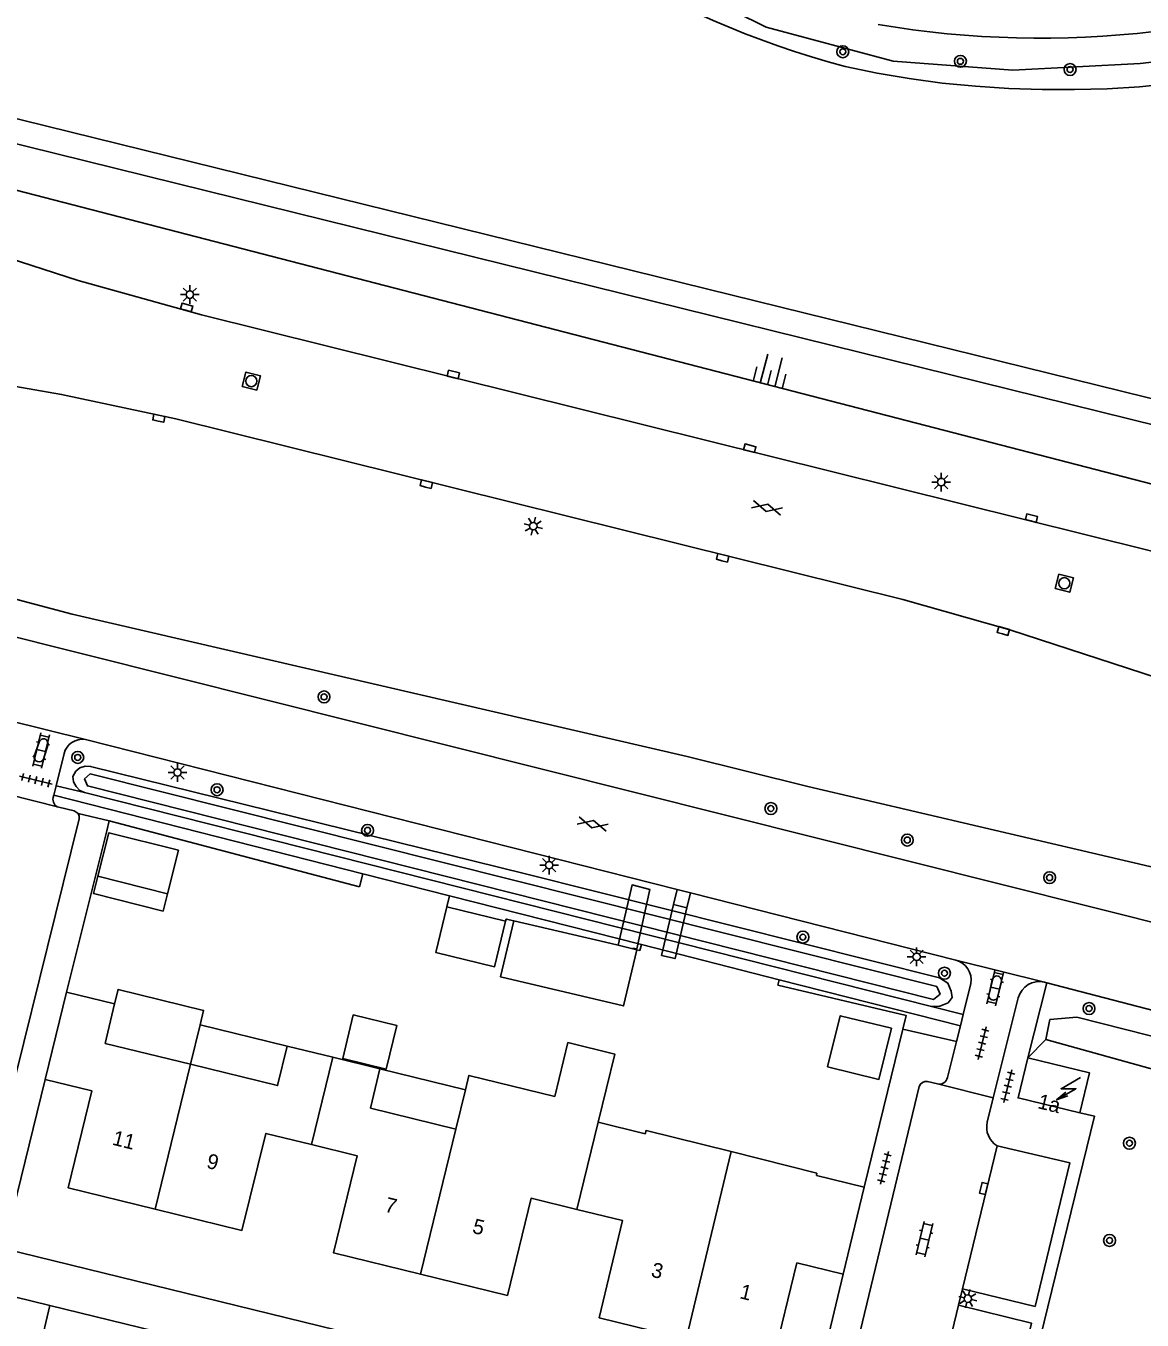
# Model space of a CAD drawing. Extents: x 128000 to 131008, y 398996 to 402500.
# Drawn here: x 128513.5 to 128588.3, y 399557.4 to 399644.1 of the extents above; entities that cross this region are included whole.
import ezdxf

# ---------------------------------------------------------------- set-up
doc = ezdxf.new("R2010")
doc.units = 0
for name, color, linetype in [('gg-afsc-erfafscheiding', 7, 'Continuous'), ('gg-afsc-muur', 7, 'Continuous'), ('gg-anno-huisnummerreeks BGT', 7, 'Continuous'), ('gg-bbg-gedigitaliseerde bebouwing', 7, 'Continuous'), ('gg-bbg-gedigitaliseerde bijgebouw', 7, 'Continuous'), ('gg-bbg-hoofdgebouw', 7, 'Continuous'), ('gg-bbg-luifel en loopbrug', 7, 'Continuous'), ('gg-bbg-tussenscheiding', 7, 'Continuous'), ('gg-knt-BGT kruinlijn', 7, 'Continuous'), ('gg-knt-onverhard', 7, 'Continuous'), ('gg-knt-verharding', 7, 'Continuous'), ('gg-knt-verharding nz', 7, 'Continuous'), ('gg-kntw-beschoeiing', 7, 'Continuous'), ('gg-kntw-bovenkant insteek waterloop', 7, 'Continuous'), ('gg-kntw-greppel-droge sloot', 7, 'Continuous'), ('gg-kntw-midden sloot', 7, 'Continuous'), ('gg-kntw-waterlijn', 7, 'Continuous'), ('gg-kwrk-kunstwerk niveau 01', 7, 'Continuous'), ('gt-grn-groengrens', 7, 'Continuous'), ('gt-grn-groengrens NZ', 7, 'Continuous'), ('gt-symb-boom', 7, 'Continuous'), ('gt-symb-gesloten verharding', 7, 'Continuous'), ('gt-symb-klinker verharding', 7, 'Continuous'), ('gt-symb-kolk', 7, 'Continuous'), ('gt-symb-lichtmast', 7, 'Continuous'), ('gt-symb-rioolschacht', 7, 'Continuous'), ('gt-symb-talud symbool', 7, 'Continuous'), ('gt-symb-tegel verharding', 7, 'Continuous'), ('gt-symb-trafo symbool', 7, 'Continuous')]:
    doc.layers.add(name, color=color, linetype=linetype)

# ---------------------------------------------------------------- blocks, each defined once
blk = doc.blocks.new('gt0-BOOM')
at = {"layer": 'gt-symb-boom'}
for radius in [0.4, 0.2]:
    blk.add_circle((0, 0), radius, dxfattribs=at)
blk = doc.blocks.new('gt0-KL1')
at = {"layer": 'gt-symb-klinker verharding'}
for p, q in [((-1.15, 0.3), (1.15, 0.3)), ((-1, -0.3), (-1, 0.3)), ((-0.5, 0.3), (-0.5, 0.45)), ((0, -0.3), (0, 0.3)), ((0.5, 0.3), (0.5, 0.45)), ((1, -0.3), (1, 0.3)), ((-1.15, -0.3), (1.15, -0.3)), ((-0.5, -0.45), (-0.5, -0.3)), ((0.5, -0.45), (0.5, -0.3))]:
    blk.add_line(p, q, dxfattribs=at)
blk = doc.blocks.new('gt0-TEG1')
at = {"layer": 'gt-symb-tegel verharding'}
for p, q in [((-1.125, 0), (1.125, 0)), ((-0.9, -0.25), (-0.9, 0.25)), ((-0.45, -0.25), (-0.45, 0.25)), ((0, -0.25), (0, 0.25)), ((0.45, -0.25), (0.45, 0.25)), ((0.9, -0.25), (0.9, 0.25))]:
    blk.add_line(p, q, dxfattribs=at)
blk = doc.blocks.new('gt0-LMAST')
at = {"layer": 'gt-symb-lichtmast'}
for p, q in [((-0.182, 0.173), (-0.447, 0.438)), ((-0.005, 0.246), (-0.005, 0.621)), ((0.172, 0.173), (0.437, 0.438)), ((-0.255, -0.004), (-0.63, -0.004)), ((-0.182, -0.181), (-0.447, -0.446)), ((-0.005, -0.254), (-0.005, -0.629)), ((0.437, -0.446), (0.172, -0.181)), ((0.245, -0.004), (0.62, -0.004))]:
    blk.add_line(p, q, dxfattribs=at)
blk.add_circle((-0.005, -0.004), 0.25, dxfattribs=at)
blk = doc.blocks.new('gt0-KOLK')
at = {"layer": 'gt-symb-kolk'}
blk.add_lwpolyline([(0, 0), (0.375, 0), (0.375, 0.4), (-0.375, 0.4), (-0.375, 0), (0, 0)], dxfattribs=at)
blk = doc.blocks.new('gt0-TALUD_1')
at = {"layer": 'gt-symb-talud symbool'}
for p, q in [((-1, -1), (-1, 0)), ((-0.5, -2), (-0.5, 0)), ((0.5, -2), (0.5, 0)), ((1, -1), (1, 0)), ((0, -1), (0, 0))]:
    blk.add_line(p, q, dxfattribs=at)
blk = doc.blocks.new('gt0-RS')
at = {"layer": 'gt-symb-rioolschacht'}
blk.add_lwpolyline([(-0.5, -0.5), (0.5, -0.5), (0.5, 0.5), (-0.5, 0.5)], close=True, dxfattribs=at)
blk.add_circle((0, 0), 0.375, dxfattribs=at)
blk = doc.blocks.new('gt0-GESVH1')
at = {"layer": 'gt-symb-gesloten verharding'}
for p, q in [((-0.992, -0.261), (0.008, 0.239)), ((0.008, -0.261), (-0.992, 0.239)), ((0.008, 0.239), (1.008, -0.261)), ((1.008, 0.239), (0.008, -0.261))]:
    blk.add_line(p, q, dxfattribs=at)
blk = doc.blocks.new('gt0-HSP')
at = {"layer": 'gt-symb-trafo symbool'}
for points in [[(0.771, 0.746), (-0.529, -0.004), (0.471, -0.004), (-0.829, -0.754)], [(-0.217, -0.24), (-0.829, -0.754), (-0.077, -0.48)]]:
    blk.add_lwpolyline(points, dxfattribs=at)

msp = doc.modelspace()

# ---------------------------------------------------------------- linework, layer by layer
at = {"layer": 'gg-afsc-erfafscheiding'}
for p, q in [((128519.13, 399590.87), (128535.897, 399586.464)), ((128518.964, 399590.205), (128516.27, 399579.4))]:
    msp.add_line(p, q, dxfattribs=at)
msp.add_lwpolyline([(128572.28, 399576.92), (128572.504, 399577.833), (128563.909, 399579.863)], dxfattribs=at)
at = {"layer": 'gg-afsc-muur'}
for p, q in [((128554.668, 399582.188), (128554.465, 399582.237)), ((128569.69, 399566.34), (128572.28, 399576.92))]:
    msp.add_line(p, q, dxfattribs=at)
msp.add_lwpolyline([(128546.226, 399584.179), (128545.717, 399584.298), (128545.673, 399584.166)], dxfattribs=at)
at = {"layer": 'gg-bbg-gedigitaliseerde bebouwing'}
for p, q in [((128524.568, 399574.573), (128518.85, 399575.97)), ((128534.107, 399575.04), (128531.051, 399575.786)), ((128537.26, 399574.27), (128534.107, 399575.04)), ((128536.62, 399571.63), (128537.26, 399574.27)), ((128542.986, 399572.868), (128542.339, 399570.228)), ((128536.62, 399571.63), (128542.339, 399570.228)), ((128551.868, 399570.693), (128555.03, 399569.92)), ((128566.527, 399567.265), (128560.782, 399568.731))]:
    msp.add_line(p, q, dxfattribs=at)
for points in [[(128524.568, 399574.573), (128530.404, 399573.144), (128531.051, 399575.786)], [(128551.868, 399570.693), (128552.987, 399575.255), (128549.849, 399576.025), (128548.964, 399572.413), (128543.22, 399573.822), (128542.986, 399572.868)], [(128560.782, 399568.731), (128555.081, 399570.129), (128555.03, 399569.92)]]:
    msp.add_lwpolyline(points, dxfattribs=at)
at = {"layer": 'gg-bbg-gedigitaliseerde bijgebouw'}
msp.add_line((128523.029, 399585.993), (128518.374, 399587.166), dxfattribs=at)
msp.add_lwpolyline([(128523.029, 399585.993), (128523.761, 399588.903), (128519.107, 399590.075), (128518.374, 399587.166)], dxfattribs=at)
at = {"layer": 'gg-bbg-hoofdgebouw'}
for p, q in [((128516.27, 399579.4), (128514.84, 399573.56)), ((128519.49, 399578.61), (128516.27, 399579.4)), ((128518.85, 399575.97), (128519.49, 399578.61)), ((128566.49, 399567.12), (128566.527, 399567.265)), ((128569.69, 399566.34), (128566.49, 399567.12)), ((128568.29, 399560.5), (128569.69, 399566.34))]:
    msp.add_line(p, q, dxfattribs=at)
for points in [[(128580.64, 399575.001), (128580, 399572.32), (128584.13, 399571.32)], [(128584.13, 399571.32), (128584.77, 399574), (128580.64, 399575.001)], [(128514.84, 399573.56), (128517.97, 399572.79), (128516.38, 399566.3), (128522.203, 399564.869)], [(128522.203, 399564.869), (128528.02, 399563.44), (128529.62, 399569.94), (128532.674, 399569.19)], [(128532.674, 399569.19), (128535.73, 399568.44), (128534.14, 399561.94), (128539.968, 399560.516)], [(128539.968, 399560.516), (128545.8, 399559.09), (128547.38, 399565.59), (128550.44, 399564.846)], [(128550.44, 399564.846), (128553.51, 399564.1), (128551.93, 399557.59), (128557.768, 399556.164)], [(128557.768, 399556.164), (128563.6, 399554.74), (128565.18, 399561.26), (128568.29, 399560.5)]]:
    msp.add_lwpolyline(points, dxfattribs=at)
at = {"layer": 'gg-bbg-luifel en loopbrug'}
for p, q in [((128541.738, 399585.109), (128545.673, 399584.166)), ((128550.817, 399583.102), (128546.226, 399584.179)), ((128551.993, 399582.837), (128550.817, 399583.102)), ((128553.221, 399582.539), (128551.993, 399582.837)), ((128554.195, 399582.303), (128553.221, 399582.539)), ((128554.465, 399582.237), (128554.195, 399582.303)), ((128525.212, 399577.211), (128524.568, 399574.573)), ((128525.212, 399577.211), (128531.051, 399575.786)), ((128537.26, 399574.27), (128542.986, 399572.868))]:
    msp.add_line(p, q, dxfattribs=at)
for points in [[(128518.374, 399587.166), (128518.081, 399586.002), (128522.736, 399584.83), (128523.029, 399585.993)], [(128545.673, 399584.166), (128544.94, 399581.104), (128541.005, 399582.047), (128541.738, 399585.109)], [(128546.226, 399584.179), (128545.34, 399580.418), (128553.578, 399578.476), (128554.465, 399582.237)], [(128519.49, 399578.61), (128519.728, 399579.581), (128525.449, 399578.181), (128525.212, 399577.211)], [(128535.47, 399577.871), (128538.387, 399577.168), (128537.684, 399574.252), (128534.767, 399574.955), (128535.47, 399577.871)], [(128567.242, 399574.39), (128570.671, 399573.551), (128571.51, 399576.979), (128568.081, 399577.819), (128567.242, 399574.39)]]:
    msp.add_lwpolyline(points, dxfattribs=at)
at = {"layer": 'gg-bbg-tussenscheiding'}
for p, q in [((128532.674, 399569.19), (128534.107, 399575.04)), ((128522.203, 399564.869), (128524.568, 399574.573)), ((128550.44, 399564.846), (128551.868, 399570.693)), ((128539.968, 399560.516), (128542.339, 399570.228)), ((128557.768, 399556.164), (128560.782, 399568.731))]:
    msp.add_line(p, q, dxfattribs=at)
at = {"layer": 'gg-knt-BGT kruinlijn'}
msp.add_line((128502.498, 399635.812), (128623.42, 399604.526), dxfattribs=at)
at = {"layer": 'gg-knt-onverhard'}
msp.add_arc((128581.493, 399708.045), 64.741, 260.34403, 293.17735, dxfattribs=at)
at = {"layer": 'gg-knt-verharding'}
for p, q in [((128512.32, 399597.621), (128517.537, 399596.321)), ((128514.438, 399596.141), (128514.1, 399595.22)), ((128514.738, 399595.011), (128515.03, 399596.02)), ((128557.167, 399586.28), (128517.537, 399596.321)), ((128516.109, 399595.381), (128515.577, 399593.233)), ((128515.577, 399593.233), (128515.42, 399592.601)), ((128515.751, 399591.786), (128512.322, 399592.66)), ((128515.42, 399592.601), (128515.38, 399592.44)), ((128517.04, 399591.361), (128519.13, 399590.87)), ((128519.13, 399590.87), (128518.964, 399590.205)), ((128556.91, 399585.263), (128557.167, 399586.28)), ((128558.066, 399586.052), (128557.167, 399586.28)), ((128558.066, 399586.052), (128557.813, 399585.052)), ((128575.83, 399581.551), (128558.066, 399586.052)), ((128575.83, 399581.551), (128581.769, 399580.078)), ((128578.269, 399580.231), (128578.05, 399579.26)), ((128576.321, 399577.904), (128576.84, 399579.99)), ((128578.64, 399579.101), (128578.879, 399580.081)), ((128581.93, 399580.03), (128580.64, 399575.001)), ((128581.93, 399580.03), (128581.769, 399580.078)), ((128578.336, 399572.314), (128580.01, 399579.02)), ((128576.133, 399577.147), (128576.321, 399577.904)), ((128572.28, 399576.92), (128575.87, 399576.09)), ((128575.87, 399576.09), (128576.133, 399577.147)), ((128575.87, 399576.09), (128575.26, 399573.68)), ((128514.84, 399573.56), (128512.692, 399564.8)), ((128573.94, 399573.41), (128574.6, 399573.25)), ((128574.6, 399573.25), (128578.336, 399572.314)), ((128568.1, 399551.17), (128573.38, 399573.081)), ((128578.336, 399572.314), (128577.93, 399570.69)), ((128565.53, 399549.13), (128568.29, 399560.5)), ((128509.44, 399559.817), (128515.154, 399558.42)), ((128576.009, 399558.428), (128576.277, 399559.533)), ((128515.154, 399558.42), (128514.012, 399553.54)), ((128515.154, 399558.42), (128564.831, 399546.272))]:
    msp.add_line(p, q, dxfattribs=at)
for points in [[(128492.703, 399634.461), (128499.462, 399632.565), (128506.196, 399630.581), (128517.05, 399627.08), (128525.32, 399624.77), (128614.18, 399602.67), (128618.463, 399601.732), (128622.829, 399600.968)], [(128621.03, 399590.124), (128579.44, 399603.67), (128572.28, 399605.7), (128523.59, 399617.81), (128515.94, 399619.44), (128501.631, 399621.928), (128497.943, 399622.631)], [(128615.399, 399576.485), (128615.66, 399577.39), (128480.487, 399611.313)], [(128517.04, 399591.361), (128517.113, 399591.188), (128517.11, 399591.001), (128510.73, 399565.281)], [(128517.04, 399591.361), (128516.78, 399591.54), (128515.751, 399591.786)], [(128581.93, 399580.03), (128614.01, 399571.67), (128614.22, 399572.399)], [(128580.17, 399550.92), (128585.11, 399571.1), (128584.13, 399571.32)], [(128578.593, 399569.113), (128583.47, 399567.964), (128581.132, 399558.353), (128576.277, 399559.533)], [(128512.692, 399564.8), (128512.06, 399562.22), (128565.53, 399549.13)], [(128574.86, 399553.679), (128579.725, 399552.487), (128580.89, 399557.235), (128576.009, 399558.428)]]:
    msp.add_lwpolyline(points, dxfattribs=at)
for centre, radius, start, end in [((128514.731, 399596.063), 0.303, 351.73795, 165.15868), ((128517.32, 399595.096), 1.244, 79.97078, 166.74011), ((128514.435, 399595.164), 0.339, 170.43309, 333.29075), ((128515.903, 399592.304), 0.54, 165.47107, 253.65953), ((128575.472, 399580.212), 1.386, 350.76647, 75.04097), ((128578.577, 399580.169), 0.314, 343.80237, 168.56758), ((128581.438, 399578.636), 1.479, 77.08195, 164.97002), ((128578.344, 399579.175), 0.306, 163.8584, 345.97676), ((128573.85, 399572.922), 0.496, 79.5634, 161.30507), ((128574.723, 399573.783), 0.547, 257.06343, 349.10627), ((128579.34, 399570.355), 1.449, 166.62051, 238.98506)]:
    msp.add_arc(centre, radius, start, end, dxfattribs=at)
at = {"layer": 'gg-knt-verharding nz'}
for p, q in [((128576.277, 399559.533), (128578.593, 399569.113)), ((128574.86, 399553.679), (128576.009, 399558.428))]:
    msp.add_line(p, q, dxfattribs=at)
at = {"layer": 'gg-kntw-beschoeiing'}
msp.add_line((128502.74, 399640.42), (128622.506, 399610.89), dxfattribs=at)
for points in [[(128607.536, 399644.895), (128605.5, 399644.006), (128603.423, 399643.22), (128601.309, 399642.538), (128597.001, 399641.408), (128594.78, 399640.947), (128592.544, 399640.566), (128590.296, 399640.264), (128588.13, 399640.053), (128585.957, 399639.923), (128583.781, 399639.867), (128581.604, 399639.874), (128579.371, 399639.946), (128577.14, 399640.081), (128574.915, 399640.293), (128572.701, 399640.596)], [(128572.701, 399640.596), (128570.556, 399640.971), (128568.423, 399641.42)]]:
    msp.add_lwpolyline(points, dxfattribs=at)
msp.add_arc((128583.808, 399699.986), 60.553, 185.69458, 255.28175, dxfattribs=at)
at = {"layer": 'gg-kntw-bovenkant insteek waterloop'}
msp.add_line((128517.485, 399592.784), (128574.196, 399578.433), dxfattribs=at)
msp.add_lwpolyline([(128574.196, 399578.433), (128574.761, 399578.463), (128575.311, 399578.686), (128575.578, 399579.043), (128575.519, 399579.474), (128575.296, 399580.009), (128574.731, 399580.366), (128547.012, 399587.316), (128517.883, 399594.524), (128517.51, 399594.549), (128517.162, 399594.424), (128516.889, 399594.201), (128516.691, 399593.853), (128516.74, 399593.48), (128516.914, 399593.181), (128517.162, 399592.908), (128517.485, 399592.784)], dxfattribs=at)
at = {"layer": 'gg-kntw-greppel-droge sloot'}
for points in [[(128583.934, 399577.729), (128582.124, 399577.558), (128581.854, 399576.218)], [(128635.847, 399563.256), (128636.073, 399564.317), (128614.401, 399569.99), (128583.934, 399577.729)], [(128581.854, 399576.218), (128613.011, 399567.574), (128614.344, 399568.095), (128635.847, 399563.256)]]:
    msp.add_lwpolyline(points, dxfattribs=at)
at = {"layer": 'gg-kntw-midden sloot'}
msp.add_lwpolyline([(128499.736, 399609.202), (128516.644, 399604.724), (128557.833, 399595.187), (128565.918, 399593.182), (128588.829, 399587.823), (128601.71, 399584.632), (128619.44, 399580.541)], dxfattribs=at)
at = {"layer": 'gg-kntw-waterlijn'}
msp.add_lwpolyline([(128517.852, 399594.035), (128574.545, 399579.785), (128574.775, 399579.272), (128574.339, 399578.9), (128517.664, 399593.219), (128517.475, 399593.7), (128517.852, 399594.035)], dxfattribs=at)
at = {"layer": 'gg-kwrk-kunstwerk niveau 01'}
msp.add_line((128557.813, 399585.052), (128556.91, 399585.263), dxfattribs=at)
for points in [[(128553.221, 399582.539), (128554.144, 399586.584), (128555.325, 399586.288), (128554.455, 399582.293), (128554.202, 399582.339), (128554.195, 399582.303)], [(128557.813, 399585.052), (128557.023, 399581.653), (128556.12, 399581.864), (128556.91, 399585.263)]]:
    msp.add_lwpolyline(points, dxfattribs=at)
at = {"layer": 'gt-grn-groengrens'}
for p, q in [((128515.577, 399593.233), (128517.485, 399592.784)), ((128536.118, 399587.333), (128515.42, 399592.601)), ((128535.897, 399586.464), (128536.118, 399587.333)), ((128541.928, 399585.854), (128536.118, 399587.333)), ((128541.738, 399585.109), (128541.928, 399585.854)), ((128554.769, 399582.585), (128541.928, 399585.854)), ((128554.668, 399582.188), (128554.769, 399582.585)), ((128564.004, 399580.234), (128554.769, 399582.585)), ((128563.909, 399579.863), (128564.004, 399580.234)), ((128576.133, 399577.147), (128564.004, 399580.234)), ((128574.196, 399578.433), (128576.321, 399577.904))]:
    msp.add_line(p, q, dxfattribs=at)
for points in [[(128605.91, 399645.69), (128597.038, 399642.646), (128588.165, 399641.602), (128579.641, 399641.167), (128571.639, 399641.776), (128563.115, 399644.038), (128556.852, 399647.169)], [(128623.363, 399608.914), (128501.603, 399639.009), (128501.27, 399639.75)]]:
    msp.add_lwpolyline(points, dxfattribs=at)
at = {"layer": 'gt-grn-groengrens NZ'}
msp.add_line((128581.854, 399576.218), (128580.64, 399575.001), dxfattribs=at)

# ---------------------------------------------------------------- block references
at = {"layer": 'gt-symb-boom'}
for p in [(128568.257, 399642.396), (128576.13, 399641.756), (128583.474, 399641.208), (128533.514, 399599.179), (128517.019, 399595.124), (128526.353, 399592.959), (128563.44, 399591.701), (128536.431, 399590.239), (128572.577, 399589.588), (128582.109, 399587.072), (128565.582, 399583.087), (128575.065, 399580.671), (128584.746, 399578.304), (128587.455, 399569.282), (128586.121, 399562.765)]:
    msp.add_blockref('gt0-BOOM', p, dxfattribs=at)
at = {"layer": 'gt-symb-gesloten verharding'}
for p, rotation in [((128563.175, 399611.856), -13.952823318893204), ((128551.504, 399590.671), -13.952823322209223)]:
    msp.add_blockref('gt0-GESVH1', p, dxfattribs=dict(at, rotation=rotation))
at = {"layer": 'gt-symb-klinker verharding', "rotation": 76.46414363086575}
for p in [(128514.57, 399595.583), (128578.462, 399579.673), (128573.721, 399562.86)]:
    msp.add_blockref('gt0-KL1', p, dxfattribs=at)
at = {"layer": 'gt-symb-kolk'}
for p, rotation in [((128524.261, 399625.076), -15.606930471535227), ((128542.123, 399620.585), -13.952823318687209), ((128522.411, 399617.654), -12.062746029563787), ((128561.978, 399615.644), -13.952823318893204), ((128540.318, 399613.24), -13.952823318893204), ((128580.845, 399610.963), -13.952823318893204), ((128560.163, 399608.305), -13.952823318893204), ((128578.954, 399603.401), -15.787947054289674), ((128577.5, 399566.295), -103.59156043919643)]:
    msp.add_blockref('gt0-KOLK', p, dxfattribs=dict(at, rotation=rotation))
at = {"layer": 'gt-symb-lichtmast'}
for p in [(128524.534, 399626.132), (128574.854, 399613.573), (128523.709, 399594.12), (128548.596, 399587.914), (128573.208, 399581.774)]:
    msp.add_blockref('gt0-LMAST', p, dxfattribs=at)
for p, rotation in [((128547.534, 399610.621), -13.952823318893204), ((128576.629, 399558.861), -103.59156043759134)]:
    msp.add_blockref('gt0-LMAST', p, dxfattribs=dict(at, rotation=rotation))
at = {"layer": 'gt-symb-rioolschacht', "rotation": -13.952823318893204}
for p in [(128528.648, 399620.333), (128583.091, 399606.795)]:
    msp.add_blockref('gt0-RS', p, dxfattribs=at)
at = {"layer": 'gt-symb-talud symbool', "xscale": 1.0002324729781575, "yscale": 1.0002324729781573, "rotation": 165.6442150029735}
msp.add_blockref('gt0-TALUD_1', (128563.217, 399620.069), dxfattribs=at)
at = {"layer": 'gt-symb-tegel verharding'}
for p, rotation in [((128514.212, 399593.594), -13.952823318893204), ((128577.587, 399575.983), 75.99155651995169), ((128579.309, 399573.1), 75.99155651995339), ((128571.045, 399567.632), 75.99155651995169)]:
    msp.add_blockref('gt0-TEG1', p, dxfattribs=dict(at, rotation=rotation))
at = {"layer": 'gt-symb-trafo symbool'}
msp.add_blockref('gt0-HSP', (128583.401, 399572.933), dxfattribs=at)

# ---------------------------------------------------------------- texts
at = {"layer": 'gg-anno-huisnummerreeks BGT'}
for s, rotation, p in [('1a', 346.4, (128581.251, 399571.636)), ('11', 346.2, (128519.28, 399569.19)), ('9', 346.2, (128525.591, 399567.641)), ('7', 346.3, (128537.525, 399564.715)), ('5', 346.2, (128543.395, 399563.282)), ('3', 346.3, (128555.359, 399560.355)), ('1', 346.3, (128561.298, 399558.905))]:
    msp.add_text(s, height=1, rotation=rotation, dxfattribs=at).set_placement(p)

doc.saveas('drawing.dxf')
